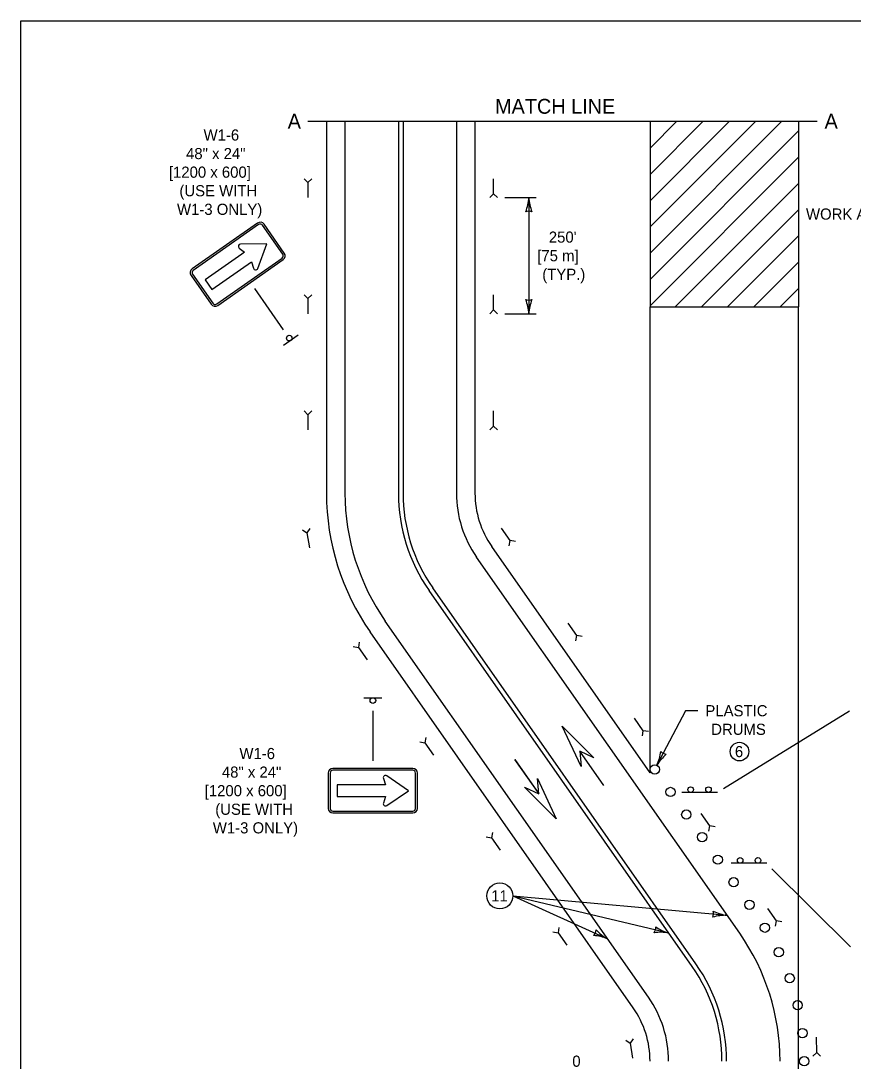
# Model space of a CAD drawing. Extents: x 49991.4 to 50021, y 49987.6 to 50011.4.
# Drawn here: x 49999.38 to 50003.87, y 49993.4 to 49999 of the extents above; entities that cross this region are included whole.
import ezdxf

# ---------------------------------------------------------------- set-up
doc = ezdxf.new("R2010")
doc.units = 0
for name, color, linetype in [('Level 1', 7, 'Continuous'), ('Level 2', 7, 'Continuous'), ('Level 3', 7, 'Continuous'), ('Level 6', 7, 'Continuous')]:
    doc.layers.add(name, color=color, linetype=linetype)

msp = doc.modelspace()

# ---------------------------------------------------------------- linework, layer by layer
at = {"layer": 'Level 1'}
for p, q in [((50001.0297, 49998.459), (50001.0297, 49996.4566)), ((50001.1297, 49998.459), (50001.1297, 49996.4566)), ((50001.4172, 49998.459), (50001.4172, 49996.4566)), ((50001.4422, 49998.459), (50001.4422, 49996.4566)), ((50001.7297, 49998.459), (50001.7297, 49996.4566)), ((50001.8297, 49998.459), (50001.8297, 49996.4566)), ((50002.7727, 49998.459), (50002.7727, 49997.459)), ((50002.7727, 49997.7483), (50003.4834, 49998.459)), ((50002.7727, 49997.8897), (50003.342, 49998.459)), ((50002.7727, 49998.0311), (50003.2006, 49998.459)), ((50002.7727, 49998.1725), (50003.0592, 49998.459)), ((50002.7727, 49998.3139), (50002.9178, 49998.459)), ((50002.7727, 49998.4554), (50002.7763, 49998.459)), ((50003.5727, 49998.459), (50003.5727, 49997.459)), ((50002.7727, 49997.6069), (50003.5727, 49998.4069)), ((50002.7727, 49997.4655), (50003.5727, 49998.2655)), ((50000.9094, 49998.1495), (50000.9299, 49998.129)), ((50000.9502, 49998.1495), (50000.9299, 49998.129)), ((50000.9299, 49998.129), (50000.9299, 49998.0476)), ((50001.9297, 49998.068), (50001.9297, 49998.1494)), ((50002.9077, 49997.459), (50003.5727, 49998.124)), ((50001.9094, 49998.0475), (50001.9297, 49998.068)), ((50001.9502, 49998.0475), (50001.9297, 49998.068)), ((50003.0492, 49997.459), (50003.5727, 49997.9825)), ((50000.6588, 49997.9104), (50000.3066, 49997.6638)), ((50000.6646, 49997.9023), (50000.3123, 49997.6557)), ((50000.7944, 49997.7429), (50000.6854, 49997.8986)), ((50000.8026, 49997.7487), (50000.6936, 49997.9043)), ((50003.1906, 49997.459), (50003.5727, 49997.8411)), ((50000.5602, 49997.7759), (50000.589, 49997.7542)), ((50000.7089, 49997.799), (50000.5674, 49997.7978)), ((50000.6594, 49997.6664), (50000.7089, 49997.799)), ((50000.5744, 49997.7439), (50000.3757, 49997.6049)), ((50000.4385, 49997.4754), (50000.7907, 49997.722)), ((50000.4442, 49997.4672), (50000.7965, 49997.7138)), ((50000.589, 49997.7542), (50000.5744, 49997.7439)), ((50000.4125, 49997.5524), (50000.6257, 49997.7017)), ((50000.6257, 49997.7017), (50000.6363, 49997.6671)), ((50003.332, 49997.459), (50003.5727, 49997.6997)), ((50000.3004, 49997.629), (50000.4094, 49997.4734)), ((50000.3086, 49997.6348), (50000.4176, 49997.4791)), ((50000.3757, 49997.6049), (50000.4125, 49997.5524)), ((50003.4734, 49997.459), (50003.5727, 49997.5583)), ((50000.9094, 49997.5245), (50000.9299, 49997.504)), ((50000.9502, 49997.5245), (50000.9299, 49997.504)), ((50000.9299, 49997.504), (50000.9299, 49997.4226)), ((50001.9297, 49997.443), (50001.9297, 49997.5244)), ((50001.9094, 49997.4225), (50001.9297, 49997.443)), ((50001.9502, 49997.4225), (50001.9297, 49997.443)), ((50002.7727, 49994.9522), (50002.7727, 49997.459)), ((50002.7727, 49997.459), (50003.5727, 49997.459)), ((50003.5727, 49991.4704), (50003.5727, 49997.459)), ((50000.8777, 49997.3063), (50000.7991, 49997.2512)), ((50000.9094, 49996.8995), (50000.9299, 49996.879)), ((50000.9502, 49996.8995), (50000.9299, 49996.879)), ((50000.9299, 49996.879), (50000.9299, 49996.7976)), ((50001.9297, 49996.818), (50001.9297, 49996.8994)), ((50001.9094, 49996.7975), (50001.9297, 49996.818)), ((50001.9502, 49996.7975), (50001.9297, 49996.818)), ((50000.9009, 49996.2599), (50000.9247, 49996.2432)), ((50000.9411, 49996.2669), (50000.9247, 49996.2432)), ((50002.0195, 49996.2022), (50001.9728, 49996.2689)), ((50000.9247, 49996.2432), (50000.9387, 49996.1631)), ((50002.0147, 49996.1738), (50002.0195, 49996.2022)), ((50002.0481, 49996.1972), (50002.0195, 49996.2022)), ((50002.7727, 49994.9522), (50001.9202, 49996.1697)), ((50003.2557, 49994.0879), (50001.8382, 49996.1123)), ((50002.9998, 49993.9087), (50001.5823, 49995.9331)), ((50003.0202, 49993.923), (50001.6027, 49995.9474)), ((50002.7642, 49993.7437), (50001.3467, 49995.7681)), ((50002.378, 49995.6902), (50002.3313, 49995.7569)), ((50002.6822, 49993.6863), (50001.2647, 49995.7107)), ((50001.2069, 49995.6542), (50001.2021, 49995.6258)), ((50002.3732, 49995.6618), (50002.378, 49995.6902)), ((50002.4066, 49995.6852), (50002.378, 49995.6902)), ((50001.1735, 49995.6308), (50001.2021, 49995.6258)), ((50001.2021, 49995.6258), (50001.2488, 49995.5591)), ((50001.2317, 49995.3558), (50001.3277, 49995.3558)), ((50002.7365, 49995.1782), (50002.6898, 49995.2449)), ((50001.5653, 49995.1422), (50001.5605, 49995.1138)), ((50002.7317, 49995.1498), (50002.7365, 49995.1782)), ((50002.7651, 49995.1732), (50002.7365, 49995.1782)), ((50001.5319, 49995.1188), (50001.5605, 49995.1138)), ((50001.5605, 49995.1138), (50001.6072, 49995.0471)), ((50002.0434, 49995.0233), (50002.173, 49994.8383)), ((50002.0436, 49995.0235), (50002.1732, 49994.8384)), ((50002.5234, 49994.8832), (50002.3938, 49995.0683)), ((50002.5236, 49994.8834), (50002.394, 49995.0684)), ((50001.4947, 49994.9754), (50001.0647, 49994.9754)), ((50001.4947, 49994.9654), (50001.0647, 49994.9654)), ((50001.0397, 49994.9504), (50001.0397, 49994.7604)), ((50001.0497, 49994.9504), (50001.0497, 49994.7604)), ((50001.3367, 49994.9217), (50001.3479, 49994.8874)), ((50001.4718, 49994.8554), (50001.3552, 49994.9356)), ((50001.5097, 49994.7604), (50001.5097, 49994.9504)), ((50001.5197, 49994.7604), (50001.5197, 49994.9504)), ((50001.33, 49994.8874), (50001.0876, 49994.8874)), ((50001.0876, 49994.8874), (50001.0876, 49994.8234)), ((50001.3479, 49994.8874), (50001.33, 49994.8874)), ((50001.3552, 49994.7752), (50001.4718, 49994.8554)), ((50001.0876, 49994.8234), (50001.3479, 49994.8234)), ((50001.3479, 49994.8234), (50001.3367, 49994.789)), ((50003.0395, 49994.8457), (50002.9435, 49994.8457)), ((50003.1355, 49994.8457), (50003.0395, 49994.8457)), ((50001.0647, 49994.7454), (50001.4947, 49994.7454)), ((50001.0647, 49994.7354), (50001.4947, 49994.7354)), ((50003.095, 49994.6662), (50003.0483, 49994.7329)), ((50001.9238, 49994.6302), (50001.919, 49994.6018)), ((50003.0902, 49994.6378), (50003.095, 49994.6662)), ((50003.1236, 49994.6612), (50003.095, 49994.6662)), ((50001.8904, 49994.6068), (50001.919, 49994.6018)), ((50001.919, 49994.6018), (50001.9657, 49994.5351)), ((50003.3061, 49994.4649), (50003.2101, 49994.4649)), ((50003.4021, 49994.4649), (50003.3061, 49994.4649)), ((50003.4535, 49994.1543), (50003.4068, 49994.221)), ((50003.4487, 49994.1259), (50003.4535, 49994.1543)), ((50003.4821, 49994.1493), (50003.4535, 49994.1543)), ((50002.2489, 49994.0949), (50002.2775, 49994.0899)), ((50002.2823, 49994.1183), (50002.2775, 49994.0899)), ((50002.2775, 49994.0899), (50002.3242, 49994.0232)), ((50002.6415, 49993.5134), (50002.6651, 49993.4966)), ((50002.6818, 49993.5202), (50002.6651, 49993.4966)), ((50003.6702, 49993.4465), (50003.6701, 49993.5279)), ((50002.6651, 49993.4966), (50002.6787, 49993.4163)), ((50003.65, 49993.426), (50003.6702, 49993.4465)), ((50003.6908, 49993.426), (50003.6702, 49993.4465))]:
    msp.add_line(p, q, dxfattribs=at)
for points in [[(49999.3835, 49998.9992), (50016.7501, 49998.9992), (50016.7501, 49987.7988), (49999.3835, 49987.7988)], [(50002.4011, 49994.9852), (50002.2996, 49995.2028), (50002.4696, 49995.0331), (50002.3939, 49995.0682)], [(50002.1659, 49994.9215), (50002.2674, 49994.7039), (50002.0974, 49994.8736), (50002.1731, 49994.8385)]]:
    msp.add_lwpolyline(points, close=True, dxfattribs=at)
for centre, radius in [((50000.8297, 49997.2912), 0.0152), ((50001.2797, 49995.3406), 0.0152), ((50002.7981, 49994.97), 0.025), ((50002.883, 49994.8485), 0.025), ((50002.9915, 49994.8609), 0.0152), ((50003.0875, 49994.8609), 0.0152), ((50002.968, 49994.727), 0.025), ((50003.053, 49994.6055), 0.025), ((50003.1379, 49994.4841), 0.025), ((50003.2581, 49994.4801), 0.0152), ((50003.3541, 49994.4801), 0.0152), ((50003.2229, 49994.3625), 0.025), ((50003.3078, 49994.2414), 0.025), ((50003.3913, 49994.1179), 0.025), ((50003.4658, 49993.9859), 0.025), ((50003.5249, 49993.8461), 0.025), ((50003.5678, 49993.7004), 0.025), ((50003.5937, 49993.5508), 0.025), ((50003.6032, 49993.3994), 0.025)]:
    msp.add_circle(centre, radius, dxfattribs=at)
for centre, radius, start, end in [((50000.6732, 49997.89), 0.025, 34.9943, 124.9943), ((50000.6732, 49997.89), 0.015, 34.9943, 124.9943), ((50000.5675, 49997.7856), 0.0122, 90.4749, 232.9525), ((50000.7821, 49997.7343), 0.015, 304.9943, 34.9943), ((50000.7821, 49997.7343), 0.025, 304.9943, 34.9943), ((50000.3209, 49997.6434), 0.025, 124.9943, 214.9943), ((50000.3209, 49997.6434), 0.015, 124.9943, 214.9943), ((50000.648, 49997.6707), 0.0122, 197.0361, 339.5137), ((50000.4299, 49997.4877), 0.025, 214.9943, 304.9943), ((50000.4299, 49997.4877), 0.015, 214.9943, 304.9943), ((50002.3297, 49996.4566), 1.3, 180, 215.0081), ((50002.3297, 49996.4566), 1.2, 180, 215.0081), ((50002.3297, 49996.4566), 0.9125, 180, 215.0081), ((50002.3297, 49996.4566), 0.8875, 180, 215.0081), ((50002.3297, 49996.4566), 0.6, 180, 215.0081), ((50002.3297, 49996.4566), 0.5, 180, 215.0081), ((50001.0647, 49994.9504), 0.025, 90, 180), ((50001.0647, 49994.9504), 0.015, 90, 180), ((50001.4947, 49994.9504), 0.025, 0, 90), ((50001.4947, 49994.9504), 0.015, 0, 90), ((50001.3483, 49994.9255), 0.0122, 55.4806, 197.9582), ((50001.0647, 49994.7604), 0.025, 180, 270), ((50001.0647, 49994.7604), 0.015, 180, 270), ((50001.3483, 49994.7852), 0.0122, 162.0418, 304.5194), ((50001.4947, 49994.7604), 0.025, 270, 0), ((50001.4947, 49994.7604), 0.015, 270, 0), ((50002.2727, 49993.3994), 1.2, 0, 35.0081), ((50002.2727, 49993.3994), 0.8875, 0, 35.0081), ((50002.2727, 49993.3994), 0.9125, 0, 35.0081), ((50002.2727, 49993.3994), 0.6, 0, 35.0081), ((50002.2727, 49993.3994), 0.5, 0, 35.0081)]:
    msp.add_arc(centre, radius, start, end, dxfattribs=at)
at = {"layer": 'Level 2'}
for centre, radius in [((50003.2543, 49995.0658), 0.05), ((50001.9636, 49994.289), 0.07)]:
    msp.add_circle(centre, radius, dxfattribs=at)
at = {"layer": 'Level 3'}
for p, q in [((50001.9902, 49998.0475), (50002.1597, 49998.0475)), ((50002.1197, 49998.0475), (50002.1197, 49997.4225)), ((50000.798, 49997.3365), (50000.6433, 49997.5577)), ((50001.9902, 49997.4225), (50002.1597, 49997.4225)), ((50001.2797, 49995.2854), (50001.2797, 49995.0154)), ((50002.9643, 49995.2858), (50002.8097, 49994.9921)), ((50003.0306, 49995.2858), (50002.9643, 49995.2858)), ((50003.169, 49994.8677), (50003.8471, 49995.2858)), ((50003.4292, 49994.4354), (50003.8528, 49994.0142)), ((50002.0336, 49994.289), (50003.1879, 49994.1847)), ((50002.0336, 49994.289), (50002.8733, 49994.0894)), ((50002.0336, 49994.289), (50002.5443, 49994.0578))]:
    msp.add_line(p, q, dxfattribs=at)
for centre, radius, start, end in [((50001.8976, 49998.0567), 0.2223, 337.456, 357.6395), ((50002.3524, 49998.059), 0.233, 182.8273, 202.0772), ((50002.1197, 49997.9193), 0.0548, 72.1388, 107.8612), ((50002.1197, 49997.5507), 0.0548, 252.1388, 287.8612), ((50001.887, 49997.411), 0.233, 2.8273, 22.0772), ((50002.3418, 49997.4133), 0.2223, 157.456, 177.6395), ((50002.5989, 49995.0912), 0.233, 334.8273, 354.0772), ((50003.0016, 49994.8797), 0.2223, 129.456, 149.6395), ((50002.8699, 49995.1053), 0.0548, 224.1388, 259.8612), ((50003.0601, 49994.195), 0.0548, 337.519, 13.2414), ((50003.1806, 49993.9518), 0.233, 88.2075, 107.4574), ((50003.2149, 49994.4054), 0.2223, 242.8362, 263.0197), ((50002.7486, 49994.1193), 0.0548, 328.6292, 4.3516), ((50002.9341, 49994.3032), 0.2223, 233.9464, 254.1299), ((50002.4286, 49994.113), 0.0548, 316.5918, 352.3142), ((50002.4543, 49993.8428), 0.233, 67.2803, 86.5302), ((50002.6484, 49994.2542), 0.2223, 221.909, 242.0925), ((50002.8301, 49993.8604), 0.233, 79.3177, 98.5676)]:
    msp.add_arc(centre, radius, start, end, dxfattribs=at)
at = {"layer": 'Level 6'}
msp.add_line((50000.9297, 49998.459), (50003.6727, 49998.459), dxfattribs=at)

# ---------------------------------------------------------------- texts
at = {"layer": 'Level 2'}
for s, height, p in [('MATCH LINE', 0.08, (50001.9378, 49998.499)), ('A', 0.08, (50000.821, 49998.419)), ('A', 0.08, (50003.7127, 49998.419)), ('W1-6', 0.06, (50000.368, 49998.3546)), ('48" x 24"', 0.06, (50000.2736, 49998.2546)), ('[1200 x 600]', 0.06, (50000.1811, 49998.1546)), ('(USE WITH', 0.06, (50000.2378, 49998.0546)), ('W1-3 ONLY)', 0.06, (50000.2249, 49997.9546)), ('WORK AREA', 0.06, (50003.6127, 49997.929)), ("250'", 0.06, (50002.2276, 49997.805)), ('[75 m]', 0.06, (50002.1651, 49997.705)), ('(TYP.)', 0.06, (50002.1921, 49997.605)), ('PLASTIC', 0.06, (50003.0709, 49995.2558)), ('DRUMS', 0.06, (50003.1022, 49995.1558)), ('W1-6', 0.06, (50000.561, 49995.0254)), ('6', 0.06, (50003.2298, 49995.0358)), ('48" x 24"', 0.06, (50000.4666, 49994.9254)), ('[1200 x 600]', 0.06, (50000.3741, 49994.8254)), ('(USE WITH', 0.06, (50000.4308, 49994.7254)), ('W1-3 ONLY)', 0.06, (50000.4178, 49994.6254)), ('11', 0.06, (50001.9169, 49994.259)), ('0', 0.06, (50002.3541, 49993.3694))]:
    msp.add_text(s, height=height, dxfattribs=at).set_placement(p)

doc.saveas('drawing.dxf')
